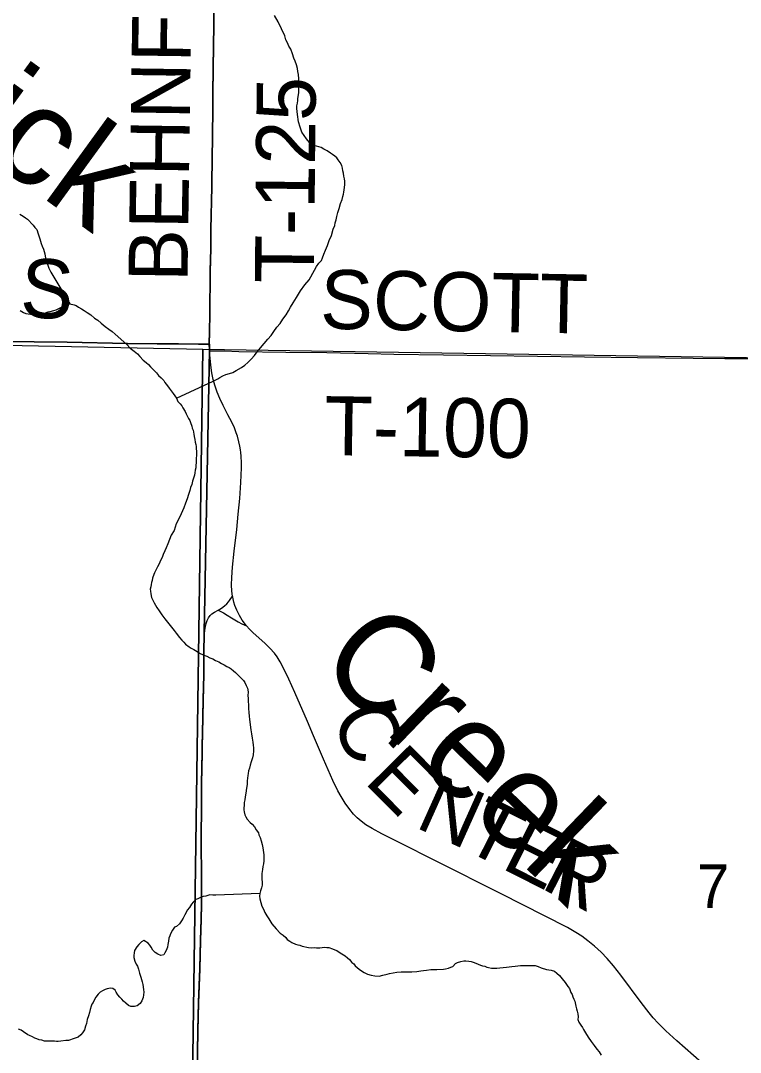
# Model space of a CAD drawing. Extents: x 0 to 34, y 0 to 22.
# Drawn here: x 6.454 to 7.146, y 14.762 to 15.755 of the extents above; entities that cross this region are included whole.
import ezdxf

# ---------------------------------------------------------------- set-up
doc = ezdxf.new("R2010")
doc.units = 0
for name, color, linetype in [('GM_X_County_Road', 7, 'Continuous'), ('GM_X_County_Road_Text', 7, 'Continuous'), ('GM_X_County_Text', 7, 'Continuous'), ('GM_X_Minor_River', 7, 'Continuous'), ('GM_X_Minor_River_Text', 7, 'Continuous'), ('GM_X_Section', 7, 'Continuous'), ('GM_X_Section_Text', 7, 'Continuous'), ('GM_X_Township_Road', 7, 'Continuous'), ('GM_X_Township_Road_Text', 7, 'Continuous')]:
    doc.layers.add(name, color=color, linetype=linetype)

msp = doc.modelspace()

# ---------------------------------------------------------------- linework, layer by layer
at = {"layer": 'GM_X_County_Road'}
msp.add_line((6.63572, 15.43754), (6.63564, 15.44407), dxfattribs=at)
for points in [[(6.63564, 15.44407), (6.62493, 15.44411), (6.60569, 15.44445), (6.58518, 15.44447), (6.55657, 15.44478), (6.49876, 15.44583), (6.46705, 15.44615), (6.43659, 15.44644), (6.39929, 15.44676), (6.38362, 15.4471), (6.36524, 15.44799)], [(6.63572, 15.43754), (6.63927, 15.43754), (6.65012, 15.43755), (6.66379, 15.43705), (6.70917, 15.43615), (6.74834, 15.43595), (6.78811, 15.43487), (6.81298, 15.43451), (6.86085, 15.43383), (6.99637, 15.43192), (7.04734, 15.43103), (7.10081, 15.43059), (7.13128, 15.43019), (7.16237, 15.43005)], [(6.6578, 15.20136), (6.65709, 15.20613), (6.65678, 15.21241), (6.65696, 15.2193), (6.65773, 15.22925), (6.65937, 15.24471), (6.66176, 15.2657), (6.66326, 15.28054), (6.66466, 15.29538), (6.66576, 15.31085), (6.66651, 15.32504), (6.6665, 15.32993), (6.66611, 15.33606), (6.66572, 15.33972), (6.66537, 15.34215), (6.66479, 15.34578), (6.66387, 15.34996), (6.66245, 15.3553), (6.66128, 15.35879), (6.65957, 15.36338), (6.65704, 15.36899), (6.65337, 15.37613), (6.6487, 15.38496), (6.64553, 15.39176), (6.64303, 15.39795), (6.64271, 15.39873), (6.64068, 15.40467), (6.63924, 15.41012), (6.638, 15.41627), (6.63699, 15.42371), (6.63604, 15.43359), (6.63572, 15.43754)], [(6.67116, 15.17284), (6.66695, 15.17846), (6.66432, 15.18277), (6.66181, 15.18787), (6.66003, 15.1926), (6.6591, 15.19561), (6.65792, 15.20053), (6.6578, 15.20136)], [(7.13324, 14.73113), (7.08513, 14.77342), (7.07461, 14.78315), (7.0671, 14.79065), (7.06249, 14.79576), (7.05847, 14.80054), (7.05085, 14.81041), (7.03125, 14.83689), (7.02432, 14.84563), (7.01823, 14.85264), (7.01224, 14.85887), (7.00588, 14.86473), (6.9997, 14.86984), (6.99372, 14.8742), (6.98801, 14.87787), (6.97995, 14.88247), (6.95792, 14.89395), (6.91626, 14.91491), (6.85352, 14.94653), (6.81794, 14.96433), (6.80129, 14.97282), (6.79199, 14.97792), (6.78614, 14.98157), (6.78156, 14.98489), (6.77772, 14.98816), (6.77418, 14.99177), (6.77056, 14.99614), (6.76618, 15.00226), (6.76211, 15.00856), (6.7591, 15.01406), (6.75424, 15.02418), (6.75196, 15.02931), (6.74527, 15.04471), (6.73571, 15.067), (6.72984, 15.08072), (6.71773, 15.10867), (6.7119, 15.12171), (6.70683, 15.13234), (6.7036, 15.13831), (6.70065, 15.14298), (6.69817, 15.14648), (6.69379, 15.15159), (6.68893, 15.1563), (6.67769, 15.16614), (6.67409, 15.16965), (6.67116, 15.17284)]]:
    msp.add_lwpolyline(points, dxfattribs=at)
at = {"layer": 'GM_X_County_Text'}
for points in [[(6.62361, 14.7449), (6.62406, 14.76292), (6.62452, 14.78343), (6.62517, 14.81078), (6.62625, 14.84308), (6.62711, 14.8704), (6.62765, 14.89088), (6.62785, 14.90517), (6.62794, 14.91698), (6.6279, 14.92816), (6.6278, 14.9387), (6.62757, 14.95724), (6.62753, 14.96398), (6.6276, 14.97328), (6.62781, 14.99502), (6.62804, 15.01928), (6.62838, 15.03854), (6.6286, 15.0491), (6.62866, 15.05904), (6.62883, 15.06829), (6.62927, 15.08691), (6.62993, 15.11488), (6.63007, 15.12482), (6.63017, 15.13228), (6.63024, 15.15093), (6.63037, 15.16212), (6.6306, 15.16646), (6.63549, 15.4381), (6.63541, 15.44462), (6.63558, 15.45605), (6.63585, 15.47288), (6.63635, 15.5133), (6.63658, 15.52635), (6.63678, 15.53442), (6.63704, 15.55432), (6.63773, 15.59535), (6.63819, 15.62584), (6.6384, 15.64022), (6.63876, 15.67468), (6.63884, 15.68587), (6.63911, 15.70887), (6.63939, 15.73188), (6.63968, 15.74991), (6.63978, 15.76732)], [(6.63978, 15.76732), (6.63968, 15.74991), (6.63939, 15.73188), (6.63911, 15.70887), (6.63884, 15.68587), (6.63876, 15.67468), (6.6384, 15.64022), (6.63819, 15.62584), (6.63773, 15.59535), (6.63704, 15.55432), (6.63678, 15.53442), (6.63658, 15.52635), (6.63635, 15.5133), (6.63585, 15.47288), (6.63558, 15.45605), (6.63541, 15.44462), (6.63549, 15.4381), (6.6306, 15.16646), (6.63037, 15.16212), (6.63024, 15.15093), (6.63017, 15.13228), (6.63007, 15.12482), (6.62993, 15.11488), (6.62927, 15.08691), (6.62883, 15.06829), (6.62866, 15.05904), (6.6286, 15.0491), (6.62838, 15.03854), (6.62804, 15.01928), (6.62781, 14.99502), (6.6276, 14.97328), (6.62753, 14.96398), (6.62757, 14.95724), (6.6278, 14.9387), (6.6279, 14.92816), (6.62794, 14.91698), (6.62785, 14.90517), (6.62765, 14.89088), (6.62711, 14.8704), (6.62625, 14.84308), (6.62517, 14.81078), (6.62452, 14.78343), (6.62406, 14.76292), (6.62361, 14.7449)]]:
    msp.add_lwpolyline(points, dxfattribs=at)
at = {"layer": 'GM_X_Minor_River'}
for points in [[(6.71561, 15.72355), (6.71381, 15.72777), (6.71199, 15.73085), (6.71054, 15.73393), (6.7091, 15.737), (6.70805, 15.74083), (6.70153, 15.75428), (6.69826, 15.76044)], [(6.6038, 15.39188), (6.63912, 15.40852), (6.6418, 15.40959), (6.64373, 15.41069), (6.64565, 15.41178), (6.64835, 15.41362), (6.65141, 15.41468), (6.65486, 15.41574), (6.65792, 15.41681), (6.66138, 15.41862), (6.66638, 15.42155), (6.66947, 15.42375), (6.67257, 15.42634), (6.67568, 15.42968), (6.6788, 15.43302), (6.68154, 15.43676), (6.68467, 15.44048), (6.68818, 15.44458), (6.69169, 15.44867), (6.69482, 15.4524), (6.69756, 15.45613), (6.70032, 15.46025), (6.70344, 15.46397), (6.70619, 15.46809), (6.70933, 15.47219), (6.71169, 15.47593), (6.71368, 15.47968), (6.71606, 15.48381), (6.71922, 15.48905), (6.72316, 15.49541), (6.72747, 15.50101), (6.73138, 15.50586), (6.73653, 15.51523), (6.73851, 15.51861), (6.74087, 15.52197), (6.74321, 15.52457), (6.74441, 15.5272), (6.74563, 15.53059), (6.74723, 15.53435), (6.74924, 15.53886), (6.75087, 15.54377), (6.75288, 15.54866), (6.75454, 15.5547), (6.75614, 15.55808), (6.75658, 15.56073), (6.75741, 15.56375), (6.75824, 15.56677), (6.75909, 15.57054), (6.76033, 15.57469), (6.76158, 15.57922), (6.76319, 15.58336), (6.76401, 15.586), (6.76444, 15.58827), (6.76487, 15.59016), (6.7653, 15.59243), (6.76536, 15.59471), (6.76581, 15.59774), (6.76588, 15.60078), (6.76555, 15.60306), (6.76486, 15.60574), (6.76454, 15.60841), (6.76383, 15.6107), (6.76351, 15.61337), (6.76282, 15.61605), (6.76136, 15.61874), (6.75953, 15.62144), (6.75806, 15.62338), (6.75619, 15.62494), (6.75395, 15.62652), (6.75208, 15.6277), (6.74872, 15.63006), (6.74572, 15.63165), (6.7431, 15.63323), (6.73858, 15.63448), (6.73555, 15.63493), (6.73366, 15.63536), (6.73183, 15.63806), (6.72887, 15.64155), (6.72447, 15.64811), (6.72268, 15.65272), (6.72129, 15.65807), (6.72031, 15.66493), (6.72, 15.66798), (6.71969, 15.67064), (6.71975, 15.6733), (6.72019, 15.67595), (6.72063, 15.6786), (6.72068, 15.6805), (6.72114, 15.68391), (6.72157, 15.68618), (6.72164, 15.68921), (6.72172, 15.69263), (6.7218, 15.69605), (6.7215, 15.69947), (6.72122, 15.70366), (6.72052, 15.70634), (6.72022, 15.70938), (6.71916, 15.71283), (6.7181, 15.71627), (6.71665, 15.71934), (6.71561, 15.72355)], [(6.45308, 15.56911), (6.45645, 15.56713), (6.45869, 15.56556), (6.46056, 15.56437), (6.46612, 15.55854), (6.46758, 15.55623), (6.46943, 15.55428), (6.47085, 15.55007), (6.47226, 15.54548), (6.47367, 15.54088), (6.47475, 15.5382), (6.47583, 15.53551), (6.47653, 15.53322), (6.47723, 15.53092), (6.47756, 15.52863), (6.47824, 15.5252), (6.47966, 15.52098), (6.48109, 15.51715), (6.4829, 15.51331), (6.50116, 15.48286)], [(6.45356, 15.47639), (6.45655, 15.47442), (6.45881, 15.47361), (6.46562, 15.47269), (6.46865, 15.47261), (6.47132, 15.47293), (6.47474, 15.47323), (6.4778, 15.4743), (6.48048, 15.47499), (6.48238, 15.47533), (6.48583, 15.47638), (6.48812, 15.47709), (6.49196, 15.4789), (6.49388, 15.47999), (6.49619, 15.48108), (6.4981, 15.48179), (6.50116, 15.48286), (6.50532, 15.482), (6.5072, 15.48119), (6.50944, 15.47962), (6.51244, 15.47803), (6.51506, 15.47645)], [(6.51506, 15.47645), (6.51805, 15.47448), (6.52141, 15.47212), (6.52513, 15.46899), (6.52812, 15.46702), (6.53148, 15.46428), (6.5352, 15.46115), (6.53893, 15.4584), (6.54191, 15.45605), (6.5449, 15.4537), (6.55307, 15.44628), (6.55605, 15.44355), (6.55938, 15.44006), (6.56311, 15.43731), (6.56647, 15.43457), (6.56869, 15.43223), (6.57164, 15.42874), (6.57462, 15.42639), (6.57686, 15.42444), (6.5787, 15.42212), (6.58093, 15.42016), (6.58278, 15.41822), (6.58464, 15.41628), (6.58648, 15.41395), (6.58908, 15.41161), (6.59168, 15.40889), (6.59277, 15.40696), (6.59535, 15.40386), (6.59682, 15.40155), (6.59866, 15.39922), (6.6005, 15.39652), (6.60234, 15.3942), (6.6038, 15.39188), (6.60525, 15.38881), (6.60747, 15.38648), (6.60895, 15.38454), (6.61004, 15.38262), (6.61224, 15.37914), (6.61332, 15.37684), (6.61441, 15.37453), (6.6155, 15.37261), (6.61659, 15.37068), (6.61731, 15.36876), (6.61874, 15.36493), (6.61907, 15.36302), (6.61979, 15.36111), (6.62012, 15.3592), (6.62045, 15.35729), (6.62078, 15.355), (6.62148, 15.35233), (6.62179, 15.34966), (6.6225, 15.34736), (6.62283, 15.34546), (6.62278, 15.34318), (6.62311, 15.34089), (6.62306, 15.33899), (6.6229, 15.33216), (6.62285, 15.32988), (6.62242, 15.32761), (6.62235, 15.32495), (6.62192, 15.32268), (6.62148, 15.32003), (6.62104, 15.31776), (6.62022, 15.31512), (6.61939, 15.3121), (6.61856, 15.30908), (6.61735, 15.30607), (6.61653, 15.30305), (6.6153, 15.29928), (6.61406, 15.29513), (6.61244, 15.29099), (6.61082, 15.28647), (6.60841, 15.28083), (6.60602, 15.27595), (6.60362, 15.27106), (6.60158, 15.26465), (6.59881, 15.26016), (6.5972, 15.25602), (6.59558, 15.25188), (6.59397, 15.24812), (6.59277, 15.24511), (6.59117, 15.24172), (6.58996, 15.23871), (6.58837, 15.23571), (6.58716, 15.2327), (6.58557, 15.2297), (6.58437, 15.22707), (6.58278, 15.22407), (6.58198, 15.22219), (6.58076, 15.2188), (6.58033, 15.21653), (6.5799, 15.21464), (6.57948, 15.21275), (6.57905, 15.21048), (6.57861, 15.20821), (6.57895, 15.2063), (6.57926, 15.20363), (6.57994, 15.2002), (6.58102, 15.19751), (6.58248, 15.1952), (6.58357, 15.19289)], [(6.58357, 15.19289), (6.58503, 15.19058), (6.58724, 15.18748), (6.5898, 15.18362), (6.59275, 15.17976), (6.6016, 15.16852), (6.60343, 15.16582), (6.60675, 15.16156), (6.60897, 15.15923), (6.61083, 15.15729), (6.61268, 15.15534), (6.61603, 15.1526), (6.6179, 15.15142), (6.62053, 15.15021), (6.6239, 15.14823), (6.62614, 15.14666), (6.62952, 15.14506), (6.63291, 15.14384), (6.63591, 15.14225), (6.63891, 15.14104), (6.64154, 15.13945), (6.64454, 15.13824), (6.64716, 15.13666), (6.64979, 15.13546), (6.65241, 15.13388), (6.65466, 15.13268), (6.65653, 15.1315), (6.65876, 15.12954), (6.66063, 15.12798), (6.6636, 15.12525), (6.66619, 15.12253), (6.66842, 15.12019), (6.66951, 15.11827), (6.67097, 15.11557), (6.67204, 15.11289), (6.67272, 15.10945), (6.67263, 15.10566), (6.67296, 15.10337), (6.67288, 15.10033), (6.67318, 15.09652), (6.6731, 15.09348), (6.67339, 15.08968), (6.67369, 15.08587), (6.67399, 15.08282), (6.67528, 15.07291), (6.67595, 15.0691), (6.67661, 15.0649), (6.67728, 15.06109), (6.67759, 15.05804), (6.6779, 15.05537), (6.67784, 15.05271), (6.67775, 15.04892), (6.67692, 15.0459), (6.67569, 15.04213), (6.67486, 15.03873), (6.67404, 15.03609), (6.67321, 15.03345), (6.67277, 15.0308), (6.67235, 15.02891), (6.67229, 15.02625), (6.67184, 15.0236), (6.67176, 15.02018), (6.6713, 15.01677), (6.67043, 15.01185), (6.66997, 15.00845), (6.66952, 15.00542), (6.66908, 15.00277), (6.66901, 15.00011), (6.66858, 14.99784), (6.66854, 14.99594), (6.66887, 14.99404), (6.66956, 14.99098), (6.67065, 14.98905), (6.67174, 14.98675), (6.6747, 14.98364), (6.67656, 14.98207), (6.67878, 14.97936), (6.68061, 14.97666), (6.68282, 14.97356), (6.68315, 14.97166), (6.68424, 14.96935), (6.68529, 14.96591), (6.68635, 14.96246), (6.68704, 14.9594), (6.68737, 14.95712), (6.68769, 14.95483), (6.68802, 14.95254), (6.68788, 14.94684), (6.68743, 14.94381), (6.68699, 14.94116), (6.68655, 14.93852), (6.68612, 14.93663), (6.68608, 14.93473), (6.68604, 14.93283), (6.68599, 14.93093), (6.68595, 14.92903), (6.68626, 14.92636), (6.68619, 14.92333), (6.68575, 14.92068), (6.68455, 14.91805), (6.68411, 14.9154)], [(6.64172, 14.91375), (6.6389, 14.91382), (6.63586, 14.91389), (6.63396, 14.91356), (6.63204, 14.91284), (6.62937, 14.91252), (6.62707, 14.91144), (6.62439, 14.91036), (6.62247, 14.90965), (6.61976, 14.90706), (6.61819, 14.90519), (6.61622, 14.90182), (6.61426, 14.89921), (6.61306, 14.89695), (6.61187, 14.8947), (6.61029, 14.8917), (6.60871, 14.88908), (6.60673, 14.88609), (6.60402, 14.88349), (6.6021, 14.88278), (6.60014, 14.88016), (6.59816, 14.87641), (6.59735, 14.87453), (6.59654, 14.87227), (6.5961, 14.86962), (6.59564, 14.86621), (6.5952, 14.86356), (6.59399, 14.86055), (6.5928, 14.8583), (6.59162, 14.85643), (6.58894, 14.85573), (6.58593, 14.85695), (6.58331, 14.85853), (6.58109, 14.86086), (6.57963, 14.86356), (6.57816, 14.86549), (6.57669, 14.86742), (6.57258, 14.87018), (6.57026, 14.86872), (6.56754, 14.86612), (6.5656, 14.86389), (6.56362, 14.86052), (6.56319, 14.85825), (6.56274, 14.8556), (6.5627, 14.8537), (6.56376, 14.85026), (6.5652, 14.84718), (6.56629, 14.84526), (6.56737, 14.84257), (6.56842, 14.83874), (6.56947, 14.83492), (6.57088, 14.83033), (6.57158, 14.82765), (6.57223, 14.82307), (6.57255, 14.82041), (6.57211, 14.81776), (6.57166, 14.81511), (6.57045, 14.8121), (6.56887, 14.80948), (6.56616, 14.80726), (6.56349, 14.80656), (6.56008, 14.80665), (6.55782, 14.80746), (6.55521, 14.8098), (6.55298, 14.81176), (6.55113, 14.8137), (6.54928, 14.81564), (6.54744, 14.81797), (6.54597, 14.82028), (6.54488, 14.82221), (6.54263, 14.82378), (6.54037, 14.82421), (6.53731, 14.82353), (6.5354, 14.82281), (6.53272, 14.82174), (6.53041, 14.82027), (6.52846, 14.81842), (6.52612, 14.81544), (6.52492, 14.81318), (6.52372, 14.81055), (6.52254, 14.80868), (6.52174, 14.8068), (6.52091, 14.80378), (6.52008, 14.80076), (6.51925, 14.79774), (6.51802, 14.79397), (6.51717, 14.79019), (6.51635, 14.78755), (6.51551, 14.78415), (6.51354, 14.78116), (6.51198, 14.7793), (6.50927, 14.77708), (6.50544, 14.77565), (6.50008, 14.77388), (6.49743, 14.77394), (6.49248, 14.7733), (6.49019, 14.77297), (6.4883, 14.77302)], [(6.68411, 14.9154), (6.64172, 14.91375)], [(6.68411, 14.9154), (6.68367, 14.91275), (6.68398, 14.91008), (6.68504, 14.90663), (6.6861, 14.90319), (6.68755, 14.90012), (6.68899, 14.89704), (6.69082, 14.89396), (6.69265, 14.89087), (6.69557, 14.88625), (6.69963, 14.88121), (6.70371, 14.87731), (6.70633, 14.87535), (6.70893, 14.87301), (6.7104, 14.87107), (6.71302, 14.86949), (6.71489, 14.86831), (6.71827, 14.8667), (6.72053, 14.86589), (6.72242, 14.86546), (6.72468, 14.86465), (6.73072, 14.86337), (6.73375, 14.86291), (6.73679, 14.86322), (6.73869, 14.86318), (6.74172, 14.8631), (6.74401, 14.86343), (6.74667, 14.86374), (6.74856, 14.86332), (6.75046, 14.86327), (6.75385, 14.86205), (6.75611, 14.86124), (6.75798, 14.86044), (6.76022, 14.85886), (6.76285, 14.85728), (6.76621, 14.8553), (6.76845, 14.85334), (6.77031, 14.85178), (6.77252, 14.84907), (6.77438, 14.8475), (6.77586, 14.84557), (6.77772, 14.84401), (6.77958, 14.84244), (6.78182, 14.84087), (6.78444, 14.83928), (6.78744, 14.83769), (6.79122, 14.83684), (6.79461, 14.836), (6.79879, 14.8359), (6.80222, 14.83658), (6.80642, 14.83762), (6.80871, 14.83832), (6.81215, 14.839), (6.81596, 14.83967), (6.82014, 14.83995), (6.82507, 14.83983), (6.83039, 14.84009), (6.83495, 14.84036), (6.83877, 14.84102), (6.84143, 14.84134), (6.84447, 14.84165), (6.84867, 14.84231), (6.85132, 14.84224), (6.85436, 14.84217), (6.86082, 14.8424), (6.86272, 14.84273), (6.8654, 14.84343), (6.8677, 14.84451), (6.86962, 14.84523), (6.87233, 14.84782), (6.87426, 14.84891), (6.87732, 14.84998), (6.88037, 14.85067), (6.88227, 14.85062), (6.88492, 14.85018), (6.88719, 14.84975), (6.8902, 14.84891), (6.89396, 14.8473), (6.89622, 14.84649), (6.8981, 14.84568), (6.90037, 14.84525), (6.90224, 14.84445), (6.90413, 14.84402), (6.90678, 14.84358), (6.90944, 14.84351), (6.91209, 14.84345), (6.91476, 14.84377), (6.91818, 14.84406), (6.92122, 14.84437), (6.92389, 14.84469), (6.92655, 14.845), (6.9296, 14.84531), (6.93226, 14.84563), (6.93493, 14.84594), (6.9372, 14.84589), (6.94063, 14.84619), (6.9429, 14.84613), (6.94594, 14.84606), (6.94897, 14.84599), (6.95161, 14.84516), (6.95462, 14.84395)], [(6.95462, 14.84395), (6.9599, 14.84231), (6.96443, 14.84144), (6.96745, 14.8406), (6.96968, 14.83865), (6.97228, 14.83631), (6.97487, 14.83321), (6.97782, 14.82972), (6.97892, 14.82779), (6.98039, 14.82586), (6.98186, 14.82392), (6.98258, 14.822), (6.98329, 14.82009), (6.98438, 14.81816), (6.98509, 14.81586), (6.98617, 14.81356), (6.98689, 14.81164), (6.98792, 14.80706), (6.98862, 14.80438), (6.98932, 14.80208), (6.99002, 14.79941), (6.99033, 14.79674), (6.98989, 14.79409), (6.99097, 14.7914), (6.9928, 14.7887), (6.99427, 14.78638), (6.99536, 14.78446), (6.99719, 14.78138), (6.99974, 14.77713), (7.00268, 14.77288), (7.00563, 14.76902), (7.0082, 14.76553), (7.01042, 14.76282), (7.01224, 14.75973)], [(6.4883, 14.77302), (6.4864, 14.77307), (6.48261, 14.77316), (6.47995, 14.77322), (6.47691, 14.77329), (6.47428, 14.77411), (6.47163, 14.77456), (6.46937, 14.77537), (6.46749, 14.77617), (6.46524, 14.77737), (6.46261, 14.77857), (6.46073, 14.77938), (6.45662, 14.78213), (6.45438, 14.78371), (6.45175, 14.78491)]]:
    msp.add_lwpolyline(points, dxfattribs=at)
at = {"layer": 'GM_X_Section'}
for points in [[(5.61786, 15.45978), (6.62912, 15.43932), (6.61504, 14.44194), (5.60488, 14.4601)], [(6.62912, 15.43932), (7.57037, 15.42463), (7.55508, 14.42463), (6.61504, 14.44194)]]:
    msp.add_lwpolyline(points, close=True, dxfattribs=at)
at = {"layer": 'GM_X_Township_Road'}
msp.add_line((6.63564, 15.44407), (6.63572, 15.43754), dxfattribs=at)
for points in [[(6.63564, 15.44407), (6.63582, 15.4555), (6.63608, 15.47233), (6.63659, 15.51274), (6.63681, 15.5258), (6.63702, 15.53387), (6.63727, 15.55377), (6.63797, 15.59479), (6.63843, 15.62529), (6.63863, 15.63967), (6.639, 15.67413), (6.63907, 15.68532), (6.63935, 15.70832), (6.63963, 15.73133), (6.63991, 15.74935), (6.64002, 15.76676)], [(6.36524, 15.44799), (6.38362, 15.4471), (6.39929, 15.44676), (6.43659, 15.44644), (6.46705, 15.44615), (6.49876, 15.44583), (6.55657, 15.44478), (6.58518, 15.44447), (6.60569, 15.44445), (6.62493, 15.44411), (6.63564, 15.44407)], [(6.63572, 15.43754), (6.63927, 15.43754), (6.65012, 15.43755), (6.66379, 15.43705), (6.70917, 15.43615), (6.74834, 15.43595), (6.78811, 15.43487), (6.81298, 15.43451), (6.86085, 15.43383), (6.99637, 15.43192), (7.04734, 15.43103), (7.10081, 15.43059), (7.13128, 15.43019), (7.16237, 15.43005)], [(6.6578, 15.20136), (6.65709, 15.20613), (6.65678, 15.21241), (6.65696, 15.2193), (6.65773, 15.22925), (6.65937, 15.24471), (6.66176, 15.2657), (6.66326, 15.28054), (6.66466, 15.29538), (6.66576, 15.31085), (6.66651, 15.32504), (6.6665, 15.32993), (6.66611, 15.33606), (6.66572, 15.33972), (6.66537, 15.34215), (6.66479, 15.34578), (6.66387, 15.34996), (6.66245, 15.3553), (6.66128, 15.35879), (6.65957, 15.36338), (6.65704, 15.36899), (6.65337, 15.37613), (6.6487, 15.38496), (6.64553, 15.39176), (6.64303, 15.39795), (6.64271, 15.39873), (6.64068, 15.40467), (6.63924, 15.41012), (6.638, 15.41627), (6.63699, 15.42371), (6.63604, 15.43359), (6.63572, 15.43754)], [(6.64404, 15.188), (6.64701, 15.18995), (6.65003, 15.19218), (6.65213, 15.1941), (6.65382, 15.19596), (6.6549, 15.19743), (6.6578, 15.20136)], [(6.6243, 14.76237), (6.62476, 14.78288), (6.62541, 14.81023), (6.62649, 14.84253), (6.62735, 14.86984), (6.62788, 14.89032), (6.62808, 14.90461), (6.62817, 14.91643), (6.62814, 14.92761), (6.62804, 14.93815), (6.6278, 14.95669), (6.62776, 14.96343), (6.62783, 14.97272), (6.62804, 14.99447), (6.62828, 15.01872), (6.62862, 15.03799), (6.62884, 15.04855), (6.6289, 15.05848), (6.62906, 15.06774), (6.6295, 15.08636), (6.63017, 15.11433), (6.63031, 15.12427), (6.63041, 15.13173), (6.63047, 15.15037), (6.6306, 15.16156), (6.63084, 15.16591), (6.63141, 15.17083), (6.63227, 15.17506), (6.63327, 15.17799), (6.63466, 15.18078), (6.63611, 15.18277), (6.63789, 15.18449), (6.64045, 15.18621), (6.64404, 15.188)], [(6.64404, 15.188), (6.64535, 15.18746), (6.64651, 15.18685), (6.64892, 15.18553), (6.65267, 15.18321), (6.65668, 15.18058), (6.66315, 15.17664), (6.66687, 15.1747), (6.67116, 15.17284)]]:
    msp.add_lwpolyline(points, dxfattribs=at)

# ---------------------------------------------------------------- texts
at = {"layer": 'GM_X_County_Road_Text'}
for s, rotation, p in [('S', 357.08289, (6.45276, 15.4703)), ('C', 292.97746, (6.75224, 15.08516)), ('E', 314.68581, (6.78347, 15.02278)), ('N', 335.83753, (6.83207, 14.97959)), ('T', 333.22317, (6.87707, 14.95941)), ('E', 333.20976, (6.91501, 14.94027)), ('R', 332.78825, (6.95285, 14.92116))]:
    msp.add_text(s, height=0.05682, rotation=rotation, dxfattribs=at).set_placement(p)
at = {"layer": 'GM_X_Minor_River_Text'}
for s, height, rotation, p in [('Lick', 0.094759, 324.04129, (6.34113, 15.6821)), ('Creek', 0.094767, 316.03654, (6.73697, 15.13525))]:
    msp.add_text(s, height=height, rotation=rotation, dxfattribs=at).set_placement(p)
at = {"layer": 'GM_X_Section_Text'}
msp.add_text('7', height=0.04186, rotation=0.00001, dxfattribs=at).set_placement((7.10448, 14.9014))
at = {"layer": 'GM_X_Township_Road_Text'}
for s, rotation, p in [('BEHNFELDT', 89.17949, (6.61443, 15.50371)), ('T-125', 89.4387, (6.73601, 15.5024)), ('SCOTT', 358.92444, (6.74174, 15.45898)), ('T-100', 359.1608, (6.74587, 15.33722))]:
    msp.add_text(s, height=0.056818, rotation=rotation, dxfattribs=at).set_placement(p)

doc.saveas('drawing.dxf')
